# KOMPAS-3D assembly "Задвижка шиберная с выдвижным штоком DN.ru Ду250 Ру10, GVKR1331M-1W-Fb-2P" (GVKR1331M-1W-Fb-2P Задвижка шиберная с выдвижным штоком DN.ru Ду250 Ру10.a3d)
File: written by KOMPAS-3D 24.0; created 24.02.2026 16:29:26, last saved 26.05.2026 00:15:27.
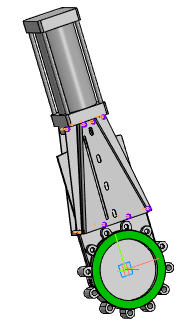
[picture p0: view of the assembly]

Document properties: Автор: R2D2; Полное имя файла: E:\Работа\Зайцев\GVKR1331M-1W-Fb-2P Задвижка шиберная с выдвижным штоком DN.ru Ду50-300 Ру16-10-6 с пневмоприводом\исходные материалы\DN250\GVKR1331M-1W-Fb-2P Задвижка шиберная с выдвижным штоком DN.ru Ду250 Ру10.a3d

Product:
- Component [detail]: Затвор дисковый DN.ru Ду Ру  | qty 1  | pos. 1  | Масса: 18.2; Раздел спецификации: Прочие изделия; Примечание: D050-23732; Автор: R2D2; source file: Задвижка шиберная РЕЗЬБОВОЙ DN.ru Ду Ру.m3d
- Component [detail]: Пневмоцилиндр  | qty 1  | pos. 2  | Масса: 88.034437; Автор: R2D2; source file: Пневмоцилиндр.m3d
- Component [standard]: Hexagon head screw ISO 4017 - М10 x 25  | qty 8  | pos. 5  | Масса: 0.026096; Раздел спецификации: Стандартные изделия; Рассекать на разрезах: no
- Component [detail]: лист  | qty 2  | pos. 3  | Масса: 4.141971; Раздел спецификации: Прочие изделия; Примечание: D040-08800; Автор: R2D2; source file: лист.m3d
- Component [detail]: шибер  | qty 1  | pos. 4  | Масса: 7.348726; Раздел спецификации: Прочие изделия; Примечание: D040-08800; Автор: R2D2; source file: шибер.m3d
- Component [standard]: Hexagon head screw ISO 4017 - М8 x 16  | qty 8  | Масса: 0.012085; Раздел спецификации: Стандартные изделия; Рассекать на разрезах: no
- Part/product: Задвижка шиберная с выдвижным штоком DN.ru Ду250 Ру10  | designation GVKR1331M-1W-Fb-2P
    Масса: 51
    Раздел спецификации: Прочие изделия
    Примечание: D040-08798

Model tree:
1. Точка:1  (with: Ребро.Отверстие в листовом теле:2)
     X = -55.0538; Y = 209.994; Z = 59.3454
2. Точка:2  (with: Ребро.Отверстие в листовом теле:3)
     X = 55.0538; Y = 209.994; Z = 59.3454
3. Точка:3  (with: Ребро.Отверстие в листовом теле:4)
     X = 157.356; Y = 210.139; Z = 34.0581
4. Точка:4  (with: Ребро.Отверстие в листовом теле:5)
     X = -81.8724; Y = 624.72; Z = 36.4298
5. Точка:5  (with: Ребро.Отверстие в листовом теле:6)
     X = -20.1578; Y = 624.507; Z = 73.5735
6. Точка:6  (with: Ребро.Отверстие в листовом теле:7)
     X = 20.1578; Y = 624.507; Z = 73.5735
7. Точка:7  (with: Ребро.Отверстие в листовом теле:8)
     X = 81.8724; Y = 624.72; Z = 36.4298
8. Массив по точкам:1
9. Экземпляр ( 6 )
10. Экземпляр ( 4 )
11. Экземпляр ( 1 )
12. Экземпляр ( 7 )
13. Экземпляр ( 3 )
14. Экземпляр ( 5 )
15. Экземпляр ( 2 )
16. Контекстная связь:1  (with: Эскиз:7, Грань.Элемент выдавливания:6, Ребро.Элемент выдавливания:6, Ребро.Элемент выдавливания:12, Контекстная связь (лист (1)):1)
17. Контекстная связь:2  (with: Эскиз:6, Грань.Элемент выдавливания:15, Ребро.Элемент выдавливания:15, Контекстная связь (лист (1)):2)
18. Контекстная связь:3  (with: Эскиз:5, Грань.Элемент выдавливания:1, Вершина.Элемент выдавливания:15, Контекстная связь (шибер):3, Грань.Элемент выдавливания:8, Грань.Линейчатая обечайка:1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)
     Ориентация = 2; Ориентация = 2; Ориентация = 2; Ориентация = 2; Ориентация = 2; Ориентация = 2; Ориентация = 2; Ориентация = 2; Ориентация = 2

Expressions: D050-23732; D040-08800
Referenced files in E:\Работа\Зайцев\GVKR1331M-1W-Fb-2P Задвижка шиберная с выдвижным штоком DN.ru Ду50-300 Ру16-10-6 с пневмоприводом\исходные материалы\DN250\: Задвижка шиберная РЕЗЬБОВОЙ DN.ru Ду Ру.m3d, Пневмоцилиндр.m3d, лист.m3d, шибер.m3d
Referenced files in C:\Program Files\ASCON\KOMPAS-3D v24\Libs\PolynomLib\DATA\vault\Methods\Kompas\3D\: PLib_Bolt_1_ISO_1100.m3d
Referenced files in E:\Работа\Зайцев\GVKR1331E-1W-Fb-2P Задвижка шиберная DN.ru Ду50-300 Ру16-10-6\исходные материалы\DN80\: лист.m3d
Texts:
  Hexagon head screw
  BOSimple***PART:f114febc-ab7b-6638-bb5e-15f0e2e47160***SHORTLOC:A259_7B16EF33AB1642D2[16;1,5;25;10;-;Undefined]
  BOSimple***PART:17775d1c-e7de-f283-40f0-d40789f7f59e***SHORTLOC:A259_7B16EF33AB1642D2[13;1,25;16;8;-;Undefined]
  Программные изделия  и базы данных
  GVKR1331M-1W-Fb-2P
  Hexagon head screw ISO 4017 - М10 x 25 (1)
  hole1
  hole2
  лист (1)
  лист (2)
  Hexagon head screw ISO 4017 - М8 x 16 (1)
  Hexagon head screw ISO 4017 - М8 x 16 (2)
  Hexagon head screw ISO 4017 - М8 x 16 (3)
  Hexagon head screw ISO 4017 - М8 x 16 (4)
  Hexagon head screw ISO 4017 - М8 x 16 (5)
  Hexagon head screw ISO 4017 - М8 x 16 (6)
  Hexagon head screw ISO 4017 - М8 x 16 (7)
  Hexagon head screw ISO 4017 - М8 x 16 (8)
  Ось Y.Начало координат
  Плоскость ZY.Начало координат
  Плоскость ZX.Начало координат
  Плоскость XY.Начало координат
